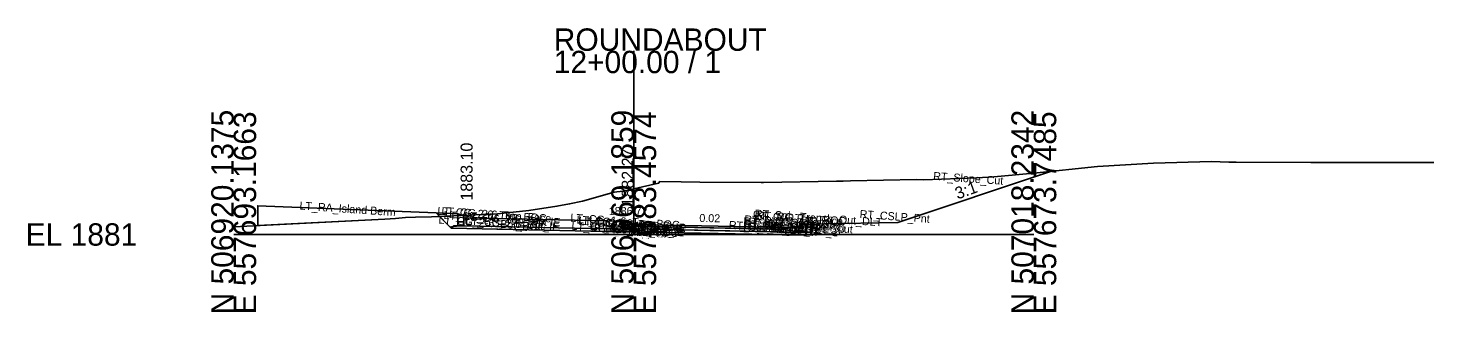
# Model space of a CAD drawing. Extents: x -36 to 140, y -10 to 2515.
# Drawn here: x -35.7 to 140, y 1990.3 to 2025.8 of the extents above; entities that cross this region are included whole.
import ezdxf

# ---------------------------------------------------------------- set-up
doc = ezdxf.new("R2010")
doc.units = 0
for name, color, linetype in [('Default', 7, 'Continuous'), ('Exist Cross Section Cell', 7, 'Continuous'), ('Exist XS Center Line Elevation Label', 7, 'Continuous'), ('Exist XS Ground Line', 7, 'Continuous'), ('Prop CMT Conc Surface', 7, 'Continuous'), ('Prop CMT Concrete Structures', 7, 'Continuous'), ('Prop CMT Pvmt Course 1', 7, 'Continuous'), ('Prop CMT Pvmt Course 1 CG', 7, 'Continuous'), ('Prop CMT Pvmt Course 2', 7, 'Continuous'), ('Prop CMT Pvmt Course 3', 7, 'Continuous'), ('Prop CMT Pvmt Course 4', 7, 'Continuous'), ('Prop CMT Slope Grass', 7, 'Continuous'), ('Prop CMT Subgrade Earthwork', 7, 'Continuous'), ('Prop Conc 4in Sidewalk', 7, 'Continuous'), ('Prop Conc Curb and Gutter', 7, 'Continuous'), ('Prop XS Earthwork Shape', 7, 'Continuous'), ('Prop XS Finish Grade Earthwork', 7, 'Continuous'), ('Prop XS Hydro Elevations', 7, 'Continuous'), ('Prop XS Side Slope Text', 7, 'Continuous'), ('Typical Structure Recommendation Sheet 1 CELL', 7, 'Continuous')]:
    doc.layers.add(name, color=color, linetype=linetype)

msp = doc.modelspace()

# ---------------------------------------------------------------- linework, layer by layer
at = {"layer": 'Exist Cross Section Cell'}
for p, q in [((40, 2000), (40, 2022.99)), ((-10, 2000), (40, 2000)), ((40, 2000), (90, 2000))]:
    msp.add_line(p, q, dxfattribs=at)
at = {"layer": 'Exist XS Ground Line'}
for p, q in [((90, 2007.66), (97.97, 2008.52)), ((97.97, 2008.52), (104.95, 2008.94)), ((104.95, 2008.94), (112.22, 2009.13)), ((112.22, 2009.13), (114.37, 2009.07)), ((114.37, 2009.07), (115.28, 2009.07)), ((115.28, 2009.07), (124.63, 2008.99)), ((124.63, 2008.99), (140, 2009))]:
    msp.add_line(p, q, dxfattribs=at)
msp.add_lwpolyline([(-10, 2000.95), (8.88, 2001.92), (10.22, 2002), (11.48, 2002.11), (12.71, 2002.17), (14.72, 2002.22), (16.58, 2002.31), (22.99, 2002.6), (26.89, 2003), (30.39, 2003.54), (31.99, 2003.82), (33.59, 2004.17), (37.55, 2005.31), (37.88, 2005.33), (38.7, 2005.43), (40, 2005.72), (43.1, 2006.42), (43.24, 2006.63), (45.91, 2006.59), (48.24, 2006.54), (55.93, 2006.49), (56.23, 2006.49), (65.32, 2006.68), (66.18, 2006.69), (67.08, 2006.7), (75.32, 2006.87), (76.27, 2006.82), (82.88, 2007.1), (85.02, 2007.22), (90, 2007.66)], dxfattribs=at)
at = {"layer": 'Prop CMT Conc Surface'}
for p, q in [((18.65, 2002.38), (18, 2002.59)), ((18, 2002.59), (18, 2001.6)), ((18, 2001.6), (18.75, 2001.6)), ((18, 2001.6), (18, 2001.1)), ((18.75, 2001.6), (18.75, 2002.24)), ((18.75, 2001.1), (18.75, 2001.6)), ((38.5, 2000.68), (38.5, 2001.68)), ((39.18, 2001.45), (38.5, 2001.68)), ((38.64, 2001.51), (38.56, 2001.51)), ((38.56, 2001.51), (38.64, 2001.43)), ((38.64, 2001.43), (38.64, 2001.51)), ((38.84, 2001.21), (38.88, 2001.06)), ((38.92, 2001.15), (38.84, 2001.21)), ((38.88, 2001.06), (38.92, 2001.15)), ((39.25, 2001.36), (39.25, 2001.37)), ((40, 2001.27), (39.34, 2001.27)), ((39.76, 2001.19), (39.8, 2001.04)), ((39.84, 2001.13), (39.76, 2001.19)), ((40, 2001.27), (40, 2000.68)), ((40, 2000.68), (40, 2001.26)), ((17.2, 2000.79), (17.5, 2001.1)), ((18, 2001.1), (17.5, 2001.1)), ((18, 2001.1), (18.75, 2001.1)), ((40, 2000.68), (38.5, 2000.68)), ((38.58, 2000.89), (38.51, 2000.88)), ((38.51, 2000.88), (38.55, 2000.77)), ((38.55, 2000.77), (38.58, 2000.89)), ((39.15, 2000.92), (39.24, 2000.87)), ((39.18, 2000.79), (39.15, 2000.92)), ((39.24, 2000.87), (39.18, 2000.79)), ((39.5, 2000.88), (39.43, 2000.86)), ((39.43, 2000.86), (39.47, 2000.75)), ((39.47, 2000.75), (39.5, 2000.88)), ((39.8, 2001.04), (39.84, 2001.13))]:
    msp.add_line(p, q, dxfattribs=at)
msp.add_lwpolyline([(40, 2000.69), (40, 2001.27)], dxfattribs=at)
msp.add_lwpolyline([(40, 2000.69), (40, 2001.27)], dxfattribs=at)
for centre in [(38.57, 2001.27), (38.58, 2001.16), (38.71, 2001.6), (38.73, 2001.15), (38.73, 2001.31), (38.85, 2001.26), (38.92, 2001.41), (39.04, 2001.27), (39.06, 2001.43), (39.11, 2001.18), (39.23, 2001.2), (39.37, 2001.18), (39.38, 2001.15), (39.5, 2001.15), (39.65, 2001.13), (39.77, 2001.25), (38.62, 2000.79), (38.64, 2001.01), (38.76, 2000.75), (38.77, 2001.02), (38.79, 2000.92), (38.92, 2000.99), (39.02, 2001.13), (39.02, 2000.73), (39.04, 2000.86), (39.07, 2000.99), (39.25, 2001.11), (39.27, 2000.73), (39.34, 2000.87), (39.34, 2000.72), (39.36, 2000.95), (39.54, 2000.78), (39.56, 2000.99), (39.68, 2000.74), (39.69, 2001), (39.71, 2000.91), (39.84, 2000.97), (39.94, 2001.12), (39.94, 2000.72), (39.96, 2000.84), (39.99, 2000.98)]:
    msp.add_circle(centre, 0.00635, dxfattribs=at)
for centre, radius, start, end in [((18.6, 2002.24), 0.146, 0, 71.5651), ((39.15, 2001.37), 0.0937, 0, 71.5651), ((39.34, 2001.36), 0.0937, 180, 270), ((38.53, 2000.69), 0.00635, 27.0386, 154.2416)]:
    msp.add_arc(centre, radius, start, end, dxfattribs=at)
at = {"layer": 'Prop CMT Concrete Structures'}
msp.add_lwpolyline([(59, 2000.89), (61, 2000.79), (61, 2001.29), (61.5, 2001.29)], dxfattribs=at)
at = {"layer": 'Prop CMT Pvmt Course 1'}
for points in [[(40, 2001.02), (40, 2001.27)], [(40, 2001.27), (59, 2000.89)], [(40, 2001.02), (40, 2001.27)], [(40, 2001.02), (40, 2001.27)], [(58, 2000.66), (40, 2001.02)], [(59, 2000.89), (59, 2000.64)], [(59, 2000.89), (59, 2000.64)]]:
    msp.add_lwpolyline(points, dxfattribs=at)
at = {"layer": 'Prop CMT Pvmt Course 1 CG'}
msp.add_lwpolyline([(59, 2000.06), (59, 2000.31)], dxfattribs=at)
at = {"layer": 'Prop CMT Pvmt Course 2'}
for points in [[(40, 2000.68), (40, 2001.02)], [(40, 2000.69), (40, 2001.02)], [(40, 2001.02), (59, 2000.64)], [(40, 2000.69), (40, 2001.02)], [(58, 2000.33), (40, 2000.69)]]:
    msp.add_lwpolyline(points, dxfattribs=at)
at = {"layer": 'Prop CMT Pvmt Course 3'}
for points in [[(40, 2000.69), (59, 2000.31)], [(59, 2000.31), (59, 1999.96)], [(59, 2000.31), (59, 1999.98)]]:
    msp.add_lwpolyline(points, dxfattribs=at)
at = {"layer": 'Prop CMT Pvmt Course 4'}
for points in [[(40, 2000.36), (40, 2000.36)], [(40, 2000.36), (40, 2000.36)], [(40, 2000.35), (40, 2000.35)], [(59, 1999.98), (59, 1999.98)], [(59, 1999.98), (59, 1999.98)]]:
    msp.add_lwpolyline(points, dxfattribs=at)
at = {"layer": 'Prop CMT Slope Grass'}
for p, q in [((72.99, 2001.52), (92.1, 2007.89)), ((-7, 2001.11), (-7, 2003.59)), ((63.73, 2001.33), (72.99, 2001.52))]:
    msp.add_line(p, q, dxfattribs=at)
msp.add_lwpolyline([(15.29, 2002.7), (-7, 2003.59)], dxfattribs=at)
at = {"layer": 'Prop CMT Subgrade Earthwork'}
for p, q in [((17.2, 2000.79), (15.29, 2002.7)), ((62.35, 1999.91), (63.73, 2001.33)), ((17.2, 2000.79), (38.49, 2000.35)), ((38.49, 2000.35), (39.98, 2000.35)), ((39.98, 2000.35), (59, 1999.95))]:
    msp.add_line(p, q, dxfattribs=at)
msp.add_lwpolyline([(59, 1999.96), (62.35, 1999.91)], dxfattribs=at)
at = {"layer": 'Prop Conc 4in Sidewalk'}
for p, q in [((18.75, 2002.09), (18.75, 2001.1)), ((18.75, 2002.09), (38.5, 2001.68)), ((18.75, 2001.1), (38.5, 2000.68))]:
    msp.add_line(p, q, dxfattribs=at)
at = {"layer": 'Prop Conc Curb and Gutter'}
for points in [[(59, 2000.89), (61, 2000.79), (61, 2001.29), (61.5, 2001.29)], [(61.5, 2001.29), (61.49, 2000.28), (59, 2000.31)], [(59, 2000.31), (59, 2000.89)], [(59, 2000.31), (61.99, 2000.27), (62.35, 1999.91)]]:
    msp.add_lwpolyline(points, dxfattribs=at)
at = {"layer": 'Prop XS Earthwork Shape'}
for points in [[(15.72, 2002.27), (16.58, 2002.31), (22.99, 2002.6), (26.89, 2003), (30.39, 2003.54), (31.99, 2003.82), (33.59, 2004.17), (37.55, 2005.31), (37.88, 2005.33), (38.7, 2005.43), (40, 2005.72), (43.1, 2006.42), (43.24, 2006.63), (45.91, 2006.59), (48.24, 2006.54), (55.93, 2006.49), (56.23, 2006.49), (65.32, 2006.68), (66.18, 2006.69), (67.08, 2006.7), (75.32, 2006.87), (76.27, 2006.82), (82.88, 2007.1), (85.02, 2007.22), (90, 2007.66), (92.1, 2007.89), (72.99, 2001.52), (63.73, 2001.33), (62.35, 1999.91), (59, 1999.95), (39.98, 2000.35), (38.49, 2000.35), (17.2, 2000.79)], [(15.72, 2002.27), (15.29, 2002.7), (-7, 2003.59), (-7, 2001.11), (8.88, 2001.92), (10.22, 2002), (11.48, 2002.11), (12.71, 2002.17), (14.72, 2002.22)]]:
    msp.add_lwpolyline(points, close=True, dxfattribs=at)
at = {"layer": 'Prop XS Finish Grade Earthwork'}
for p, q in [((15.29, 2002.7), (18, 2002.59)), ((61.5, 2001.29), (63.73, 2001.33))]:
    msp.add_line(p, q, dxfattribs=at)

# ---------------------------------------------------------------- texts
at = {"layer": 'Default'}
msp.add_text('-', height=0.0001, dxfattribs=at).set_placement((0, 1999.93))
at = {"layer": 'Exist Cross Section Cell'}
for s, p in [('ROUNDABOUT', (30, 2022.99)), ('12+00.00 / 1', (30, 2020.19)), ('EL 1881', (-36, 1998.6))]:
    msp.add_text(s, height=2.8, dxfattribs=at).set_placement(p)
for s, p in [('N 506920.1375', (-10, 1990)), ('E 557693.1663', (-7.2, 1990)), ('N 506969.1859', (40, 1990)), ('E 557683.4574', (42.8, 1990)), ('N 507018.2342', (90, 1990)), ('E 557673.7485', (92.8, 1990))]:
    msp.add_text(s, height=2.8, rotation=90, dxfattribs=at).set_placement(p)
at = {"layer": 'Exist XS Center Line Elevation Label'}
msp.add_text('1886.72', height=1, dxfattribs=at).set_placement((36.88, 2002.43))
at = {"layer": 'Prop XS Hydro Elevations'}
for s, height, rotation, p in [('1883.10', 1.5, 90, (19.86, 2004.24)), ('1882.27', 1.5, 90, (40, 2003.5)), ('0.02', 1, 358.8542, (48.19, 2001.57))]:
    msp.add_text(s, height=height, rotation=rotation, dxfattribs=at).set_placement(p)
at = {"layer": 'Prop XS Side Slope Text'}
msp.add_text('3:1', height=1.5, rotation=19.9616, dxfattribs=at).set_placement((80.47, 2004.37))
at = {"layer": 'Typical Structure Recommendation Sheet 1 CELL'}
for s, p in [('RT_Slope_Cut', (77.4, 2006.83)), ('LT_RA_Island Berm', (-1.8, 2003.13)), ('LT_CG_2-6_Top_BOC', (15.43, 2002.47)), ('LT_CG_2-6_Top_Face', (15.94, 2002.46)), ('LT_CG_2-6_Top_Gut', (16.21, 2001.95)), ('RT_CG_Top_Face', (54.84, 2001.93)), ('RT_Sub_Trench_Out_DLT', (55.08, 2002.13)), ('RT_CG_Top_BOC', (55.32, 2001.94)), ('RT_CSLP_Pnt', (68.21, 2002.07)), ('LT_CG_2-6_Bot_BOC', (15.57, 2001.38)), ('LT_CG_2-6_Top_IE', (18.8, 2001.86)), ('LT_CG_2-6_Bot_IE', (18.94, 2001.27)), ('LT_CG_1-6_Top_BOC', (32.05, 2001.62)), ('LT_CG_1-6_Bot_BOC', (32.19, 2000.6)), ('LT_CG_1-6_Top_Face', (32.82, 2001.37)), ('LT_CG_1-6_Top_Gut', (33.09, 2001.19)), ('LT_CG_1-6_Top_IE', (34.43, 2001.16)), ('LT_CG_1-6_Bot_IE', (34.57, 2000.57)), ('LT_MI_BOC', (35.04, 2000.83)), ('LT_PV2_PGL', (36.35, 2000.78)), ('LT_PV3_PGL', (36.35, 2000.44)), ('RT_Sub_OEOT_CG_1', (51.85, 2000.71)), ('RT_PV2_OEOT', (53.66, 2001.17)), ('RT_PV3_OEOT', (53.66, 2000.84)), ('RT_PV4_OEOT', (53.66, 2000.5)), ('RT_Sub_OEOT', (53.68, 2000.5)), ('RT_PV1_OEOT', (53.78, 2001.41)), ('RT_CG_Bot_IE', (53.83, 2000.82)), ('RT_CG_Top_Gut', (55.1, 2001.42)), ('RT_CG1_Shelf_Out', (55.4, 2000.98)), ('RT_CG_Bot_BOC', (55.46, 2000.93)), ('RT_Sub_OEOP', (56.92, 2000.65)), ('LT_PV4_PGL', (36.35, 2000.11)), ('LT_Sub_PGL', (36.38, 2000.11))]:
    msp.add_text(s, height=1, rotation=356, dxfattribs=at).set_placement(p)

doc.saveas('drawing.dxf')
